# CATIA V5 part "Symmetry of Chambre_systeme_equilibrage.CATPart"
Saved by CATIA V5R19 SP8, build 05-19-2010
Part number: Symmetry of Chambre_systeme_equilibrage
Bounding box of the stored display mesh (mm): x -130.438 to -75, y 64.826 to 615.434, z 1202.311 to 1314.328
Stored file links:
  G:\EU_thinkMotion\CFAO_2010\MMS_groupe2\MMS_groupe2\OK\nrosalie\nrosalie_cfao_support_d_arme_legere_final\Symmetry of Chambre_systeme_equilibrage.CATPart
  G:\EU_thinkMotion\CFAO_2010\MMS_groupe2\MMS_groupe2\OK\nrosalie\nrosalie_cfao_support_d_arme_legere_final\Chambre_systeme_equilibrage.CATPart
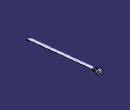
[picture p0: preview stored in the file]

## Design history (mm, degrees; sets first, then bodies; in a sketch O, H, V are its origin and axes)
Body1 (main body)
  Body2 "Corps du corps principal d'origine"
    Solid1: linked copy from another document
  Assemble1: tool Body2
